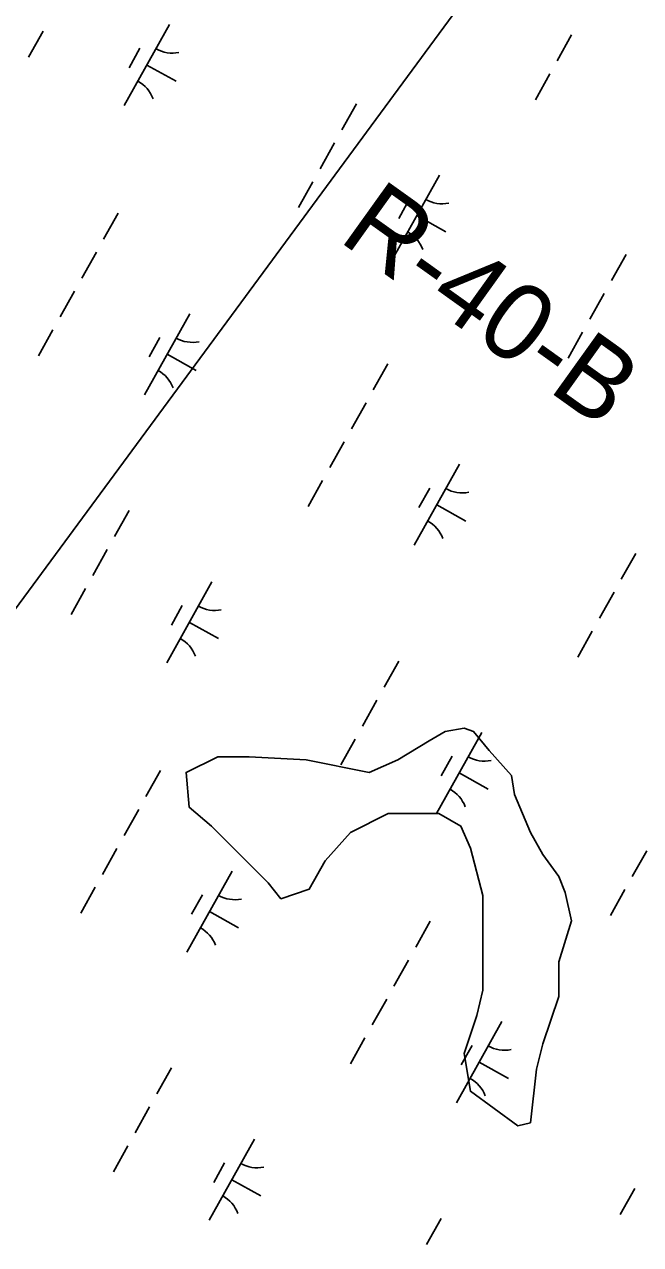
# Model space of a CAD drawing. Extents: x 3923531 to 3943530, y 207391 to 229799.
# Drawn here: x 3936854 to 3937185, y 218344 to 219001 of the extents above; entities that cross this region are included whole.
import ezdxf

# ---------------------------------------------------------------- set-up
doc = ezdxf.new("R2010")
doc.units = 0
for name, color, linetype in [('V-RIVR-RANG-IDEN', 7, 'Continuous'), ('V-TOPO-SHOR', 7, 'Continuous'), ('V-UTIL-LINE', 7, 'Continuous'), ('V-WETL-SWMP', 7, 'Continuous')]:
    doc.layers.add(name, color=color, linetype=linetype)

msp = doc.modelspace()

# ---------------------------------------------------------------- linework, layer by layer
at = {"layer": 'V-TOPO-SHOR'}
msp.add_lwpolyline([(3937126.12, 218565.55), (3937117.62, 218585.95), (3937115.92, 218596.15), (3937104.02, 218609.75), (3937095.52, 218619.95), (3937090.42, 218621.65), (3937080.22, 218619.95), (3937071.72, 218614.85), (3937054.72, 218604.65), (3937039.42, 218597.85), (3937005.42, 218604.65), (3936974.82, 218606.35), (3936957.82, 218606.35), (3936940.82, 218597.85), (3936942.52, 218579.15), (3936954.42, 218568.95), (3936966.32, 218557.05), (3936985.02, 218538.35), (3936991.82, 218529.85), (3937007.12, 218534.95), (3937015.62, 218550.25), (3937029.22, 218565.55), (3937049.62, 218575.75), (3937076.82, 218575.75), (3937088.72, 218568.95), (3937093.82, 218557.05), (3937100.62, 218531.55), (3937100.62, 218502.65), (3937100.62, 218480.55), (3937097.22, 218466.95), (3937090.42, 218446.55), (3937093.82, 218426.15), (3937119.32, 218407.45), (3937126.12, 218409.15), (3937129.52, 218438.05), (3937132.92, 218451.65), (3937141.42, 218477.15), (3937141.42, 218495.85), (3937148.22, 218517.95), (3937144.82, 218533.25), (3937141.42, 218541.75), (3937132.92, 218553.65)], close=True, dxfattribs=at)
at = {"layer": 'V-UTIL-LINE'}
msp.add_lwpolyline([(3939084.62, 223621.72), (3938057.71, 221140.48), (3938136.4, 220832.47), (3937591.63, 219695.21), (3936312.73, 217957.68), (3935106.6, 216231.89), (3934055.84, 214955.86), (3930691.13, 211497.88), (3930457.99, 211185.48)], dxfattribs=at)
at = {"layer": 'V-WETL-SWMP'}
for p, q in [((3936863.82, 218997.2), (3936856.01, 218983.23)), ((3936931.91, 219000.74), (3936907.52, 218957.09)), ((3937148.36, 218995.12), (3937140.56, 218981.15)), ((3936915.9, 218987.92), (3936910.05, 218977.44)), ((3936919.71, 218978.92), (3936935.43, 218970.14)), ((3937136.66, 218974.17), (3937128.85, 218960.2)), ((3937032.44, 218957.98), (3937024.64, 218944.01)), ((3937020.74, 218937.03), (3937012.93, 218923.06)), ((3937077.12, 218919.62), (3937052.73, 218875.97)), ((3937009.03, 218916.08), (3937001.23, 218902.11)), ((3937061.12, 218906.79), (3937055.27, 218896.32)), ((3936904.16, 218899.06), (3936896.36, 218885.09)), ((3937064.93, 218897.79), (3937080.64, 218889.01)), ((3936892.46, 218878.11), (3936884.66, 218864.14)), ((3937177.66, 218876.86), (3937169.85, 218862.89)), ((3936880.75, 218857.16), (3936872.95, 218843.19)), ((3937165.95, 218855.91), (3937158.15, 218841.94)), ((3936942.71, 218844.97), (3936918.33, 218801.32)), ((3936869.05, 218836.21), (3936861.25, 218822.24)), ((3937154.25, 218834.95), (3937146.44, 218820.99)), ((3936926.71, 218832.15), (3936920.86, 218821.67)), ((3936930.52, 218823.14), (3936946.24, 218814.37)), ((3937049.38, 218817.94), (3937041.57, 218803.97)), ((3937037.67, 218796.99), (3937029.87, 218783.02)), ((3937025.97, 218776.03), (3937018.16, 218762.07)), ((3937087.93, 218763.85), (3937063.54, 218720.2)), ((3937014.26, 218755.08), (3937006.46, 218741.11)), ((3937071.93, 218751.02), (3937066.07, 218740.55)), ((3937075.74, 218742.02), (3937091.45, 218733.24)), ((3936910.05, 218738.9), (3936902.25, 218724.93)), ((3936898.34, 218717.95), (3936890.54, 218703.98)), ((3937182.89, 218715.86), (3937175.08, 218701.89)), ((3936886.64, 218696.99), (3936878.84, 218683.03)), ((3936954.73, 218700.53), (3936930.34, 218656.88)), ((3937171.18, 218694.91), (3937163.38, 218680.94)), ((3936938.73, 218687.71), (3936932.87, 218677.23)), ((3936942.53, 218678.71), (3936958.25, 218669.93)), ((3937159.48, 218673.96), (3937151.67, 218659.99)), ((3937055.26, 218657.77), (3937047.46, 218643.81)), ((3937043.56, 218636.82), (3937035.75, 218622.85)), ((3937031.85, 218615.87), (3937024.05, 218601.9)), ((3937099.94, 218619.41), (3937075.56, 218575.76)), ((3937083.94, 218606.58), (3937078.09, 218596.11)), ((3936926.99, 218598.85), (3936919.18, 218584.89)), ((3937087.75, 218597.58), (3937103.46, 218588.8)), ((3936915.28, 218577.9), (3936907.48, 218563.93)), ((3936903.58, 218556.95), (3936895.77, 218542.98)), ((3937188.77, 218555.7), (3937180.97, 218541.73)), ((3936965.54, 218544.76), (3936941.15, 218501.11)), ((3936891.87, 218536), (3936884.07, 218522.03)), ((3936949.53, 218531.94), (3936943.68, 218521.46)), ((3937177.07, 218534.75), (3937169.26, 218520.78)), ((3936953.34, 218522.94), (3936969.06, 218514.16)), ((3937072.2, 218517.73), (3937064.4, 218503.76)), ((3937060.49, 218496.78), (3937052.69, 218482.81)), ((3937048.79, 218475.82), (3937040.99, 218461.86)), ((3937110.75, 218463.64), (3937086.36, 218419.99)), ((3937037.08, 218454.87), (3937029.28, 218440.9)), ((3937094.75, 218450.81), (3937088.89, 218440.34)), ((3936932.87, 218438.69), (3936925.07, 218424.72)), ((3937098.56, 218441.81), (3937114.27, 218433.03)), ((3936921.17, 218417.74), (3936913.36, 218403.77)), ((3936977.55, 218400.32), (3936953.16, 218356.67)), ((3936909.46, 218396.79), (3936901.66, 218382.82)), ((3936961.55, 218387.5), (3936955.69, 218377.02)), ((3936965.36, 218378.5), (3936981.07, 218369.72)), ((3937182.3, 218373.75), (3937174.49, 218359.78)), ((3937078.08, 218357.57), (3937070.28, 218343.6))]:
    msp.add_line(p, q, dxfattribs=at)
for centre, start, end in [((3936933.39, 219002.91), 240.03808, 281.58174), ((3936906.45, 218954.69), 20.03808, 61.58174), ((3937078.61, 218921.79), 240.03808, 281.58174), ((3937051.66, 218873.56), 20.03808, 61.58174), ((3936944.2, 218847.14), 240.03808, 281.58174), ((3936917.26, 218798.92), 20.03808, 61.58174), ((3937089.41, 218766.02), 240.03808, 281.58174), ((3937062.47, 218717.79), 20.03808, 61.58174), ((3936956.21, 218702.71), 240.03808, 281.58174), ((3936929.27, 218654.48), 20.03808, 61.58174), ((3937101.43, 218621.58), 240.03808, 281.58174), ((3937074.48, 218573.35), 20.03808, 61.58174), ((3936967.02, 218546.93), 240.03808, 281.58174), ((3936940.08, 218498.71), 20.03808, 61.58174), ((3937112.23, 218465.81), 240.03808, 281.58174), ((3937085.29, 218417.58), 20.03808, 61.58174), ((3936979.03, 218402.5), 240.03808, 281.58174), ((3936952.09, 218354.27), 20.03808, 61.58174)]:
    msp.add_arc(centre, 17.62, start, end, dxfattribs=at)

# ---------------------------------------------------------------- texts
at = {"layer": 'V-RIVR-RANG-IDEN'}
msp.add_text('R-40-B', height=41.5, rotation=324.40314, dxfattribs=at).set_placement((3937022.1, 218884.67))

doc.saveas('drawing.dxf')
